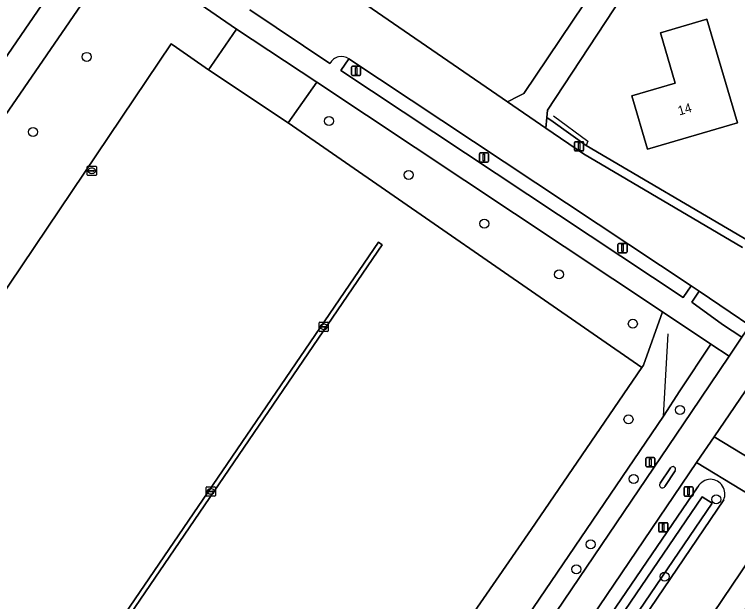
# Model space of a CAD drawing. Extents: x 157132 to 159279, y 384991 to 386650.
# Drawn here: x 158598.5 to 158676.9, y 385524.2 to 385587.8 of the extents above; entities that cross this region are included whole.
import ezdxf

# ---------------------------------------------------------------- set-up
doc = ezdxf.new("R2010")
doc.units = 0
for name, color, linetype in [('IMGEO_Boom', 7, 'Continuous'), ('IMGEO_Gemengd_bos', 7, 'Continuous'), ('IMGEO_Groenvoorziening', 7, 'Continuous'), ('IMGEO_Haag', 7, 'Continuous'), ('IMGEO_Hek', 7, 'Continuous'), ('IMGEO_Kolk', 7, 'Continuous'), ('IMGEO_Lichtmast', 7, 'Continuous'), ('IMGEO_Loofbos', 7, 'Continuous'), ('IMGEO_Oever', 7, 'Continuous'), ('IMGEO_Pand', 7, 'Continuous'), ('IMGEO_Pand_nummerreeks', 7, 'Continuous'), ('IMGEO_Parkeervlak_gesloten', 7, 'Continuous'), ('IMGEO_Rijbaan_lokaal_gesloten', 7, 'Continuous'), ('IMGEO_Sloot', 7, 'Continuous'), ('IMGEO_Verkeersbordpaal', 7, 'Continuous'), ('IMGEO_Verkeerseiland_gesloten', 7, 'Continuous'), ('IMGEO_Verkeerseiland_open', 7, 'Continuous'), ('IMGEO_Voetpad_halfverhard', 7, 'Continuous'), ('IMGEO_Voetpad_open', 7, 'Continuous'), ('IMGEO_Waterloop', 7, 'Continuous')]:
    doc.layers.add(name, color=color, linetype=linetype)

msp = doc.modelspace()

# ---------------------------------------------------------------- linework, layer by layer
at = {"layer": 'IMGEO_Boom'}
for centre in [(158606.386, 385583.201), (158632.655, 385576.242), (158600.554, 385575.065), (158641.281, 385570.409), (158649.489, 385565.13), (158657.597, 385559.623), (158665.589, 385554.274), (158670.699, 385544.939), (158665.12, 385543.916), (158665.673, 385537.459), (158674.631, 385535.247), (158661.013, 385530.373), (158659.463, 385527.672), (158669.028, 385526.874)]:
    msp.add_circle(centre, 0.489, dxfattribs=at)
at = {"layer": 'IMGEO_Gemengd_bos'}
for points in [[(158619.061, 385601.834), (158619.092, 385600.968), (158652.012, 385578.342), (158653.198, 385578.932), (158653.77, 385579.216), (158660.314, 385588.96), (158664.18, 385595.562), (158667.091, 385593.81), (158656.343, 385577.425), (158656.272, 385576.643), (158656.964, 385576.149), (158660.526, 385573.604), (158678.136, 385563.272)], [(158416.718, 385518.918), (158432.421, 385507.98), (158456.911, 385544.351), (158479.187, 385577.434), (158514.468, 385553.679), (158492.995, 385521.811), (158494.074, 385521.069), (158497.473, 385525.778), (158501.138, 385523.133), (158500.495, 385522.242), (158500, 385521.54), (158497.819, 385518.448), (158517.173, 385504.798), (158548.16, 385533.423), (158561.811, 385531.05), (158567.151, 385539), (158577.352, 385553.824), (158594.632, 385578.874), (158607.886, 385598.171), (158608.65, 385598.598), (158610.629, 385600.429)]]:
    msp.add_lwpolyline(points, dxfattribs=at)
for points in [[(158616.111, 385584.205), (158619.585, 385581.801), (158619.833, 385582.159), (158622.628, 385586.199), (158618.686, 385588.922), (158609.829, 385594.745), (158566.017, 385531.045), (158574.87, 385524.893), (158586.099, 385541.287), (158595.283, 385554.58), (158615.528, 385584.606)], [(158673.631, 385587.28), (158676.929, 385576.066), (158667.174, 385573.198), (158665.475, 385578.977), (158670.184, 385580.361), (158668.586, 385585.797)]]:
    msp.add_lwpolyline(points, close=True, dxfattribs=at)
at = {"layer": 'IMGEO_Groenvoorziening'}
for points in [[(158634.799, 385582.997), (158633.928, 385581.732), (158671.034, 385557.11), (158671.9, 385558.406)], [(158666.751, 385549.798), (158668.8, 385555.554), (158631.313, 385580.459), (158628.234, 385576.065), (158666.573, 385549.538)], [(158671.969, 385556.609), (158675.297, 385554.195), (158677.405, 385552.827), (158678.276, 385554.103), (158676.126, 385555.54), (158672.77, 385557.816)], [(158668.904, 385544.272), (158670.689, 385547.011), (158674.048, 385552.067), (158668.8, 385555.554), (158666.751, 385549.798), (158666.573, 385549.538), (158654.558, 385531.992), (158645.594, 385519.031), (158649.52, 385516.324), (158644.763, 385509.425), (158640.827, 385512.139), (158632.431, 385500), (158624.357, 385488.327), (158607.518, 385500), (158574.13, 385523.146), (158573.986, 385522.916), (158573.908, 385522.793), (158573.426, 385523.128), (158572.139, 385521.254), (158627.646, 385483.511), (158638.822, 385500)], [(158671.908, 385544.668), (158676.028, 385550.752), (158674.048, 385552.067), (158670.689, 385547.011), (158668.904, 385544.272), (158638.822, 385500), (158627.646, 385483.511), (158591.13, 385429.635), (158560.664, 385384.706), (158529.735, 385339.095), (158531.86, 385337.675), (158581.034, 385410.481)]]:
    msp.add_lwpolyline(points, close=True, dxfattribs=at)
for points in [[(158656.272, 385576.643), (158656.167, 385575.487), (158660.224, 385572.698), (158677.492, 385562.542)], [(158678.136, 385563.272), (158660.526, 385573.604), (158656.964, 385576.149), (158656.272, 385576.643)]]:
    msp.add_lwpolyline(points, dxfattribs=at)
at = {"layer": 'IMGEO_Haag'}
for points in [[(158634.799, 385582.997), (158633.928, 385581.732), (158671.034, 385557.11), (158671.9, 385558.406)], [(158631.313, 385580.459), (158628.234, 385576.065), (158666.573, 385549.538), (158666.751, 385549.798), (158668.8, 385555.554)], [(158574.13, 385523.146), (158573.986, 385522.916), (158573.908, 385522.793), (158573.426, 385523.128), (158572.139, 385521.254), (158627.646, 385483.511), (158638.822, 385500), (158668.904, 385544.272), (158670.689, 385547.011), (158674.048, 385552.067), (158668.8, 385555.554), (158666.751, 385549.798), (158666.573, 385549.538), (158654.558, 385531.992), (158645.594, 385519.031), (158649.52, 385516.324), (158644.763, 385509.425), (158640.827, 385512.139), (158632.431, 385500), (158624.357, 385488.327), (158607.518, 385500)]]:
    msp.add_lwpolyline(points, close=True, dxfattribs=at)
at = {"layer": 'IMGEO_Hek'}
for points in [[(158656.984, 385576.792), (158660.722, 385574.048), (158660.526, 385573.604)], [(158660.526, 385573.604), (158678.136, 385563.272), (158678.766, 385562.98), (158679.316, 385562.849), (158679.868, 385562.82), (158680.61, 385562.935), (158681.172, 385563.155), (158681.752, 385563.534), (158682.16, 385563.939)], [(158668.904, 385544.272), (158669.421, 385553.202)], [(158668.904, 385544.272), (158638.822, 385500), (158627.646, 385483.511)]]:
    msp.add_lwpolyline(points, dxfattribs=at)
at = {"layer": 'IMGEO_Kolk'}
for p, q in [((158606.43, 385570.426), (158606.43, 385571.278)), ((158606.505, 385571.352), (158607.357, 385571.352)), ((158606.689, 385570.846), (158606.689, 385570.858)), ((158607.127, 385570.809), (158606.729, 385570.809)), ((158606.732, 385570.895), (158607.13, 385570.895)), ((158606.918, 385571.132), (158606.943, 385571.132)), ((158607.173, 385570.858), (158607.173, 385570.846)), ((158607.431, 385571.278), (158607.431, 385570.426)), ((158607.357, 385570.352), (158606.505, 385570.352)), ((158606.941, 385570.572), (158606.916, 385570.572)), ((158631.572, 385553.526), (158631.572, 385554.378)), ((158631.647, 385554.452), (158632.499, 385554.452)), ((158632.06, 385554.232), (158632.085, 385554.232)), ((158632.573, 385554.378), (158632.573, 385553.526)), ((158632.499, 385553.452), (158631.647, 385553.452)), ((158631.831, 385553.946), (158631.831, 385553.958)), ((158632.269, 385553.909), (158631.871, 385553.909)), ((158631.874, 385553.995), (158632.272, 385553.995)), ((158632.083, 385553.672), (158632.058, 385553.672)), ((158632.315, 385553.958), (158632.315, 385553.946)), ((158619.322, 385535.679), (158619.322, 385536.531)), ((158619.397, 385536.605), (158620.249, 385536.605)), ((158619.581, 385536.099), (158619.581, 385536.111)), ((158619.624, 385536.148), (158620.022, 385536.148)), ((158619.81, 385536.385), (158619.835, 385536.385)), ((158620.065, 385536.111), (158620.065, 385536.099)), ((158620.323, 385536.531), (158620.323, 385535.679)), ((158620.249, 385535.605), (158619.397, 385535.605)), ((158620.019, 385536.062), (158619.621, 385536.062)), ((158619.833, 385535.825), (158619.808, 385535.825))]:
    msp.add_line(p, q, dxfattribs=at)
for points in [[(158606.43, 385570.426), (158606.43, 385571.278)], [(158606.505, 385571.352), (158607.357, 385571.352)], [(158607.431, 385571.278), (158607.431, 385570.426)], [(158607.357, 385570.352), (158606.505, 385570.352)], [(158631.572, 385553.526), (158631.572, 385554.378)], [(158631.647, 385554.452), (158632.499, 385554.452)], [(158632.573, 385554.378), (158632.573, 385553.526)], [(158632.499, 385553.452), (158631.647, 385553.452)], [(158619.322, 385535.679), (158619.322, 385536.531)], [(158619.397, 385536.605), (158620.249, 385536.605)], [(158620.323, 385536.531), (158620.323, 385535.679)], [(158620.249, 385535.605), (158619.397, 385535.605)]]:
    msp.add_lwpolyline(points, dxfattribs=at)
for centre, radius, start, end in [((158606.507, 385571.276), 0.0765, 91.55205, 178.44795), ((158606.507, 385571.276), 0.0765, 91.55205, 178.44795), ((158606.729, 385570.855), 0.0403, 85.87752, 175.75265), ((158606.726, 385570.845), 0.0366, 178.93798, 274.71019), ((158607.13, 385570.852), 0.043, 264.86636, 352.45326), ((158607.134, 385570.857), 0.0386, 1.73085, 96.63898), ((158607.355, 385571.276), 0.0765, 1.55205, 88.44795), ((158607.355, 385571.276), 0.0765, 1.55205, 88.44795), ((158606.507, 385570.428), 0.0765, 181.55205, 268.44795), ((158606.507, 385570.428), 0.0765, 181.55205, 268.44795), ((158607.355, 385570.428), 0.0765, 271.55205, 358.44795), ((158607.355, 385570.428), 0.0765, 271.55205, 358.44795), ((158631.649, 385554.376), 0.0765, 91.55205, 178.44795), ((158631.649, 385554.376), 0.0765, 91.55205, 178.44795), ((158632.497, 385554.376), 0.0765, 1.55205, 88.44795), ((158632.497, 385554.376), 0.0765, 1.55205, 88.44795), ((158631.649, 385553.528), 0.0765, 181.55205, 268.44795), ((158631.649, 385553.528), 0.0765, 181.55205, 268.44795), ((158631.871, 385553.955), 0.0403, 85.87752, 175.75265), ((158631.868, 385553.945), 0.0366, 178.93798, 274.71019), ((158632.272, 385553.952), 0.043, 264.86636, 352.45326), ((158632.276, 385553.957), 0.0386, 1.73085, 96.63898), ((158632.497, 385553.528), 0.0765, 271.55205, 358.44795), ((158632.497, 385553.528), 0.0765, 271.55205, 358.44795), ((158619.399, 385536.529), 0.0765, 91.55205, 178.44795), ((158619.399, 385536.529), 0.0765, 91.55205, 178.44795), ((158619.621, 385536.108), 0.0403, 85.87752, 175.75265), ((158619.618, 385536.098), 0.0366, 178.93798, 274.71019), ((158620.022, 385536.105), 0.043, 264.86636, 352.45326), ((158620.026, 385536.11), 0.0386, 1.73085, 96.63898), ((158620.247, 385536.529), 0.0765, 1.55205, 88.44795), ((158620.247, 385536.529), 0.0765, 1.55205, 88.44795), ((158619.399, 385535.681), 0.0765, 181.55205, 268.44795), ((158619.399, 385535.681), 0.0765, 181.55205, 268.44795), ((158620.247, 385535.681), 0.0765, 271.55205, 358.44795), ((158620.247, 385535.681), 0.0765, 271.55205, 358.44795)]:
    msp.add_arc(centre, radius, start, end, dxfattribs=at)
for centre, major_axis, ratio, start_param, end_param in [((158606.917, 385570.852), (-0.387, 0.002), 0.722429, 4.712389, 7.853982), ((158606.942, 385570.852), (-0.39, 0.002), 0.717154, 1.570796, 4.712389), ((158632.059, 385553.952), (-0.387, 0.002), 0.722429, 4.712389, 7.853982), ((158632.084, 385553.952), (-0.39, 0.002), 0.717154, 1.570796, 4.712389), ((158619.809, 385536.105), (-0.387, 0.002), 0.722429, 4.712389, 7.853982), ((158619.834, 385536.105), (-0.39, 0.002), 0.717154, 1.570796, 4.712389)]:
    msp.add_ellipse(centre, major_axis=major_axis, ratio=ratio, start_param=start_param, end_param=end_param, dxfattribs=at)
at = {"layer": 'IMGEO_Lichtmast'}
for p, q in [((158635.089, 385581.278), (158635.089, 385582.078)), ((158635.089, 385582.078), (158635.089, 385581.278)), ((158635.189, 385582.178), (158635.979, 385582.178)), ((158635.979, 385582.178), (158635.189, 385582.178)), ((158636.079, 385582.078), (158636.079, 385581.278)), ((158636.079, 385581.278), (158636.079, 385582.078)), ((158635.979, 385581.178), (158635.189, 385581.178)), ((158635.189, 385581.178), (158635.979, 385581.178)), ((158659.266, 385573.104), (158659.266, 385573.904)), ((158659.266, 385573.904), (158659.266, 385573.104)), ((158659.366, 385574.004), (158660.156, 385574.004)), ((158660.156, 385574.004), (158659.366, 385574.004)), ((158660.256, 385573.904), (158660.256, 385573.104)), ((158660.256, 385573.104), (158660.256, 385573.904)), ((158660.156, 385573.004), (158659.366, 385573.004)), ((158659.366, 385573.004), (158660.156, 385573.004)), ((158648.947, 385571.898), (158648.947, 385572.698)), ((158648.947, 385572.698), (158648.947, 385571.898)), ((158649.047, 385572.798), (158649.837, 385572.798)), ((158649.837, 385572.798), (158649.047, 385572.798)), ((158649.937, 385572.698), (158649.937, 385571.898)), ((158649.937, 385571.898), (158649.937, 385572.698)), ((158649.837, 385571.798), (158649.047, 385571.798)), ((158649.047, 385571.798), (158649.837, 385571.798)), ((158663.975, 385562.075), (158663.975, 385562.875)), ((158663.975, 385562.875), (158663.975, 385562.075)), ((158664.075, 385562.975), (158664.865, 385562.975)), ((158664.865, 385562.975), (158664.075, 385562.975)), ((158664.965, 385562.875), (158664.965, 385562.075)), ((158664.965, 385562.075), (158664.965, 385562.875)), ((158664.865, 385561.975), (158664.075, 385561.975)), ((158664.075, 385561.975), (158664.865, 385561.975)), ((158668.394, 385531.819), (158668.394, 385532.619)), ((158668.394, 385532.619), (158668.394, 385531.819)), ((158668.494, 385532.719), (158669.284, 385532.719)), ((158669.284, 385532.719), (158668.494, 385532.719)), ((158669.384, 385532.619), (158669.384, 385531.819)), ((158669.384, 385531.819), (158669.384, 385532.619)), ((158669.284, 385531.719), (158668.494, 385531.719)), ((158668.494, 385531.719), (158669.284, 385531.719))]:
    msp.add_line(p, q, dxfattribs=at)
for points in [[(158635.509, 385582.053), (158635.659, 385582.053), (158635.659, 385581.303), (158635.509, 385581.303), (158635.509, 385582.053)], [(158659.686, 385573.879), (158659.836, 385573.879), (158659.836, 385573.129), (158659.686, 385573.129), (158659.686, 385573.879)], [(158649.367, 385572.673), (158649.517, 385572.673), (158649.517, 385571.923), (158649.367, 385571.923), (158649.367, 385572.673)], [(158664.395, 385562.85), (158664.545, 385562.85), (158664.545, 385562.1), (158664.395, 385562.1), (158664.395, 385562.85)], [(158668.814, 385532.594), (158668.964, 385532.594), (158668.964, 385531.844), (158668.814, 385531.844), (158668.814, 385532.594)]]:
    msp.add_lwpolyline(points, dxfattribs=at)
for centre, start, end in [((158635.189, 385582.078), 90, 180), ((158635.189, 385582.078), 90, 180), ((158635.979, 385582.078), 0, 90), ((158635.979, 385582.078), 360, 90), ((158635.189, 385581.278), 180, 270), ((158635.189, 385581.278), 180, 270), ((158635.979, 385581.278), 270, 0), ((158635.979, 385581.278), 270, 0), ((158659.366, 385573.904), 90, 180), ((158659.366, 385573.904), 90, 180), ((158660.156, 385573.904), 0, 90), ((158660.156, 385573.904), 360, 90), ((158659.366, 385573.104), 180, 270), ((158659.366, 385573.104), 180, 270), ((158660.156, 385573.104), 270, 0), ((158660.156, 385573.104), 270, 0), ((158649.047, 385572.698), 90, 180), ((158649.047, 385572.698), 90, 180), ((158649.837, 385572.698), 0, 90), ((158649.837, 385572.698), 360, 90), ((158649.047, 385571.898), 180, 270), ((158649.047, 385571.898), 180, 270), ((158649.837, 385571.898), 270, 0), ((158649.837, 385571.898), 270, 0), ((158664.075, 385562.875), 90, 180), ((158664.075, 385562.875), 90, 180), ((158664.865, 385562.875), 0, 90), ((158664.865, 385562.875), 360, 90), ((158664.075, 385562.075), 180, 270), ((158664.075, 385562.075), 180, 270), ((158664.865, 385562.075), 270, 0), ((158664.865, 385562.075), 270, 0), ((158668.494, 385532.619), 90, 180), ((158668.494, 385532.619), 90, 180), ((158669.284, 385532.619), 0, 90), ((158669.284, 385532.619), 360, 90), ((158668.494, 385531.819), 180, 270), ((158668.494, 385531.819), 180, 270), ((158669.284, 385531.819), 270, 0), ((158669.284, 385531.819), 270, 0)]:
    msp.add_arc(centre, 0.1, start, end, dxfattribs=at)
at = {"layer": 'IMGEO_Loofbos'}
for points in [[(158829.534, 385770.684), (158825.89, 385765.291), (158758.28, 385665.216), (158688.968, 385562.804), (158688.692, 385563.035), (158682.812, 385554.392), (158674.409, 385542.043), (158702.865, 385524.759)], [(158702.316, 385520.276), (158702.143, 385520.922), (158701.752, 385521.463), (158672.498, 385539.233), (158554.662, 385365.305), (158526.59, 385323.554)], [(158526.115, 385320.49), (158526.494, 385322.064), (158526.708, 385322.254), (158527.65, 385322.353), (158530.805, 385326.778), (158563.335, 385375.618), (158601.84, 385432.273), (158624.577, 385466.175), (158647.655, 385500), (158672.636, 385536.613)], [(158675.44, 385535.194), (158651.568, 385500), (158630.519, 385469.342)], [(158680.176, 385526.77), (158661.45, 385500), (158624.93, 385445.662), (158623.181, 385446.733), (158658.835, 385500), (158678.392, 385528.949)]]:
    msp.add_lwpolyline(points, dxfattribs=at)
for centre, radius, start, end in [((158674.155, 385535.626), 1.812, 94.63148, 147.00101), ((158673.955, 385535.821), 1.612, 337.12473, 88.0658)]:
    msp.add_arc(centre, radius, start, end, dxfattribs=at)
at = {"layer": 'IMGEO_Oever'}
for points in [[(158672.636, 385536.613), (158647.655, 385500), (158624.577, 385466.175), (158601.84, 385432.273), (158563.335, 385375.618), (158530.805, 385326.778), (158527.65, 385322.353), (158526.708, 385322.254), (158526.494, 385322.064), (158526.115, 385320.49)], [(158572.519, 385383.258), (158590.753, 385410.188), (158601.359, 385425.531), (158630.519, 385469.342), (158651.568, 385500), (158675.44, 385535.194)]]:
    msp.add_lwpolyline(points, dxfattribs=at)
msp.add_lwpolyline([(158528.132, 385321.562), (158596.54, 385423.091), (158673.1, 385535.532), (158674.204, 385534.853), (158606.646, 385435.575), (158542.612, 385340.883), (158528.939, 385321.095)], close=True, dxfattribs=at)
for centre, radius, start, end in [((158674.155, 385535.626), 1.812, 94.63148, 147.00101), ((158673.955, 385535.821), 1.612, 337.12473, 88.0658)]:
    msp.add_arc(centre, radius, start, end, dxfattribs=at)
at = {"layer": 'IMGEO_Pand'}
msp.add_lwpolyline([(158667.174, 385573.198), (158676.929, 385576.066), (158673.631, 385587.28), (158668.586, 385585.797), (158670.184, 385580.361), (158665.475, 385578.977)], close=True, dxfattribs=at)
at = {"layer": 'IMGEO_Parkeervlak_gesloten'}
for points in [[(158666.573, 385549.538), (158628.234, 385576.065), (158619.585, 385581.801), (158616.111, 385584.205), (158615.528, 385584.606), (158595.283, 385554.58), (158586.099, 385541.287), (158574.87, 385524.893), (158575.182, 385524.676), (158574.13, 385523.146), (158607.518, 385500), (158624.357, 385488.327), (158632.431, 385500), (158640.827, 385512.139), (158645.594, 385519.031), (158654.558, 385531.992)], [(158601.97, 385509.43), (158601.537, 385509.707), (158638.024, 385563.116), (158638.427, 385562.839)]]:
    msp.add_lwpolyline(points, close=True, dxfattribs=at)
at = {"layer": 'IMGEO_Rijbaan_lokaal_gesloten'}
for points in [[(158677.492, 385562.542), (158660.224, 385572.698), (158656.167, 385575.487), (158652.012, 385578.342), (158619.092, 385600.968), (158619.061, 385601.834), (158608.023, 385608.276), (158603.015, 385611.799), (158602.195, 385612.374), (158597.172, 385615.892), (158592.17, 385619.396), (158591.18, 385620.102), (158533.536, 385659.559), (158531.086, 385661.236), (158508.177, 385676.917), (158500.285, 385682.641), (158486.116, 385692.836)], [(158624.046, 385588.306), (158632.749, 385582.498)], [(158634.799, 385582.997), (158671.9, 385558.406), (158672.77, 385557.816), (158676.126, 385555.54), (158678.276, 385554.103), (158678.853, 385553.755), (158679.428, 385553.458)], [(158672.498, 385539.233), (158672.575, 385539.348), (158674.409, 385542.043), (158682.812, 385554.392), (158682.253, 385553.991), (158681.695, 385553.635)], [(158679.428, 385553.458), (158678.853, 385553.755), (158678.276, 385554.103), (158677.405, 385552.827), (158676.028, 385550.752), (158671.908, 385544.668), (158581.034, 385410.481), (158531.86, 385337.675), (158522.865, 385324.358), (158520.349, 385320.633), (158524.026, 385318.525)], [(158526.59, 385323.554), (158554.662, 385365.305), (158672.498, 385539.233)], [(158668.544, 385536.997), (158669.671, 385538.655)], [(158670.194, 385538.346), (158669.06, 385536.646)]]:
    msp.add_lwpolyline(points, dxfattribs=at)
for points in [[(158667.091, 385593.81), (158664.18, 385595.562), (158660.314, 385588.96), (158653.77, 385579.216), (158653.198, 385578.932), (158652.012, 385578.342), (158656.167, 385575.487), (158656.272, 385576.643), (158656.343, 385577.425)], [(158622.628, 385586.199), (158619.833, 385582.159), (158619.585, 385581.801), (158628.234, 385576.065), (158631.313, 385580.459)]]:
    msp.add_lwpolyline(points, close=True, dxfattribs=at)
for centre, radius, start, end in [((158634.005, 385581.797), 1.438, 56.50827, 150.85289), ((158669.929, 385538.494), 0.304, 330.79894, 148.04999), ((158668.792, 385536.807), 0.313, 142.58167, 328.9687)]:
    msp.add_arc(centre, radius, start, end, dxfattribs=at)
at = {"layer": 'IMGEO_Sloot'}
msp.add_lwpolyline([(158678.392, 385528.949), (158658.835, 385500), (158623.181, 385446.733), (158624.93, 385445.662), (158661.45, 385500), (158680.176, 385526.77)], dxfattribs=at)
at = {"layer": 'IMGEO_Verkeersbordpaal'}
for p, q in [((158666.99, 385538.872), (158666.99, 385539.672)), ((158666.99, 385539.672), (158666.99, 385538.872)), ((158667.09, 385539.772), (158667.88, 385539.772)), ((158667.88, 385539.772), (158667.09, 385539.772)), ((158667.98, 385539.672), (158667.98, 385538.872)), ((158667.98, 385538.872), (158667.98, 385539.672)), ((158667.88, 385538.772), (158667.09, 385538.772)), ((158667.09, 385538.772), (158667.88, 385538.772)), ((158671.144, 385535.708), (158671.144, 385536.508)), ((158671.144, 385536.508), (158671.144, 385535.708)), ((158671.244, 385536.608), (158672.034, 385536.608)), ((158672.034, 385536.608), (158671.244, 385536.608)), ((158672.134, 385536.508), (158672.134, 385535.708)), ((158672.134, 385535.708), (158672.134, 385536.508)), ((158672.034, 385535.608), (158671.244, 385535.608)), ((158671.244, 385535.608), (158672.034, 385535.608))]:
    msp.add_line(p, q, dxfattribs=at)
for points in [[(158667.41, 385539.647), (158667.56, 385539.647), (158667.56, 385538.897), (158667.41, 385538.897), (158667.41, 385539.647)], [(158671.564, 385536.483), (158671.714, 385536.483), (158671.714, 385535.733), (158671.564, 385535.733), (158671.564, 385536.483)]]:
    msp.add_lwpolyline(points, dxfattribs=at)
for centre, start, end in [((158667.09, 385539.672), 90, 180), ((158667.09, 385539.672), 90, 180), ((158667.88, 385539.672), 0, 90), ((158667.88, 385539.672), 360, 90), ((158667.09, 385538.872), 180, 270), ((158667.09, 385538.872), 180, 270), ((158667.88, 385538.872), 270, 0), ((158667.88, 385538.872), 270, 0), ((158671.244, 385536.508), 90, 180), ((158671.244, 385536.508), 90, 180), ((158672.034, 385536.508), 0, 90), ((158672.034, 385536.508), 360, 90), ((158671.244, 385535.708), 180, 270), ((158671.244, 385535.708), 180, 270), ((158672.034, 385535.708), 270, 0), ((158672.034, 385535.708), 270, 0)]:
    msp.add_arc(centre, 0.1, start, end, dxfattribs=at)
at = {"layer": 'IMGEO_Verkeerseiland_gesloten'}
for points in [[(158669.671, 385538.655), (158668.544, 385536.997)], [(158669.06, 385536.646), (158670.194, 385538.346)]]:
    msp.add_lwpolyline(points, dxfattribs=at)
for centre, radius, start, end in [((158669.929, 385538.494), 0.304, 330.79894, 148.04999), ((158668.792, 385536.807), 0.313, 142.58167, 328.9687)]:
    msp.add_arc(centre, radius, start, end, dxfattribs=at)
at = {"layer": 'IMGEO_Verkeerseiland_open'}
msp.add_lwpolyline([(158638.024, 385563.116), (158601.537, 385509.707), (158601.97, 385509.43), (158638.427, 385562.839)], close=True, dxfattribs=at)
at = {"layer": 'IMGEO_Voetpad_halfverhard'}
for points in [[(158674.409, 385542.043), (158672.575, 385539.348), (158672.498, 385539.233), (158701.752, 385521.463), (158702.143, 385520.922), (158702.316, 385520.276), (158706.503, 385525.162)], [(158702.865, 385524.759), (158674.409, 385542.043)]]:
    msp.add_lwpolyline(points, dxfattribs=at)
at = {"layer": 'IMGEO_Voetpad_open'}
for points in [[(158623.624, 385590.468), (158622.734, 385589.187), (158614.043, 385594.983), (158608.65, 385598.598), (158607.886, 385598.171), (158594.632, 385578.874)], [(158566.017, 385531.045), (158609.829, 385594.745), (158618.686, 385588.922), (158622.628, 385586.199), (158631.313, 385580.459), (158668.8, 385555.554), (158674.048, 385552.067), (158676.028, 385550.752), (158677.405, 385552.827), (158675.297, 385554.195), (158671.969, 385556.609), (158672.77, 385557.816), (158671.9, 385558.406), (158671.034, 385557.11), (158633.928, 385581.732)], [(158632.749, 385582.498), (158624.046, 385588.306)], [(158633.928, 385581.732), (158634.799, 385582.997)]]:
    msp.add_lwpolyline(points, dxfattribs=at)
msp.add_arc((158634.005, 385581.797), 1.438, 56.50827, 150.85289, dxfattribs=at)
at = {"layer": 'IMGEO_Waterloop'}
msp.add_lwpolyline([(158528.132, 385321.562), (158528.939, 385321.095), (158542.612, 385340.883), (158606.646, 385435.575), (158674.204, 385534.853), (158673.1, 385535.532), (158596.54, 385423.091)], close=True, dxfattribs=at)

# ---------------------------------------------------------------- texts
at = {"layer": 'IMGEO_Pand_nummerreeks'}
msp.add_text('14', height=1, rotation=16.3835, dxfattribs=at).set_placement((158670.636, 385576.842))

doc.saveas('drawing.dxf')
